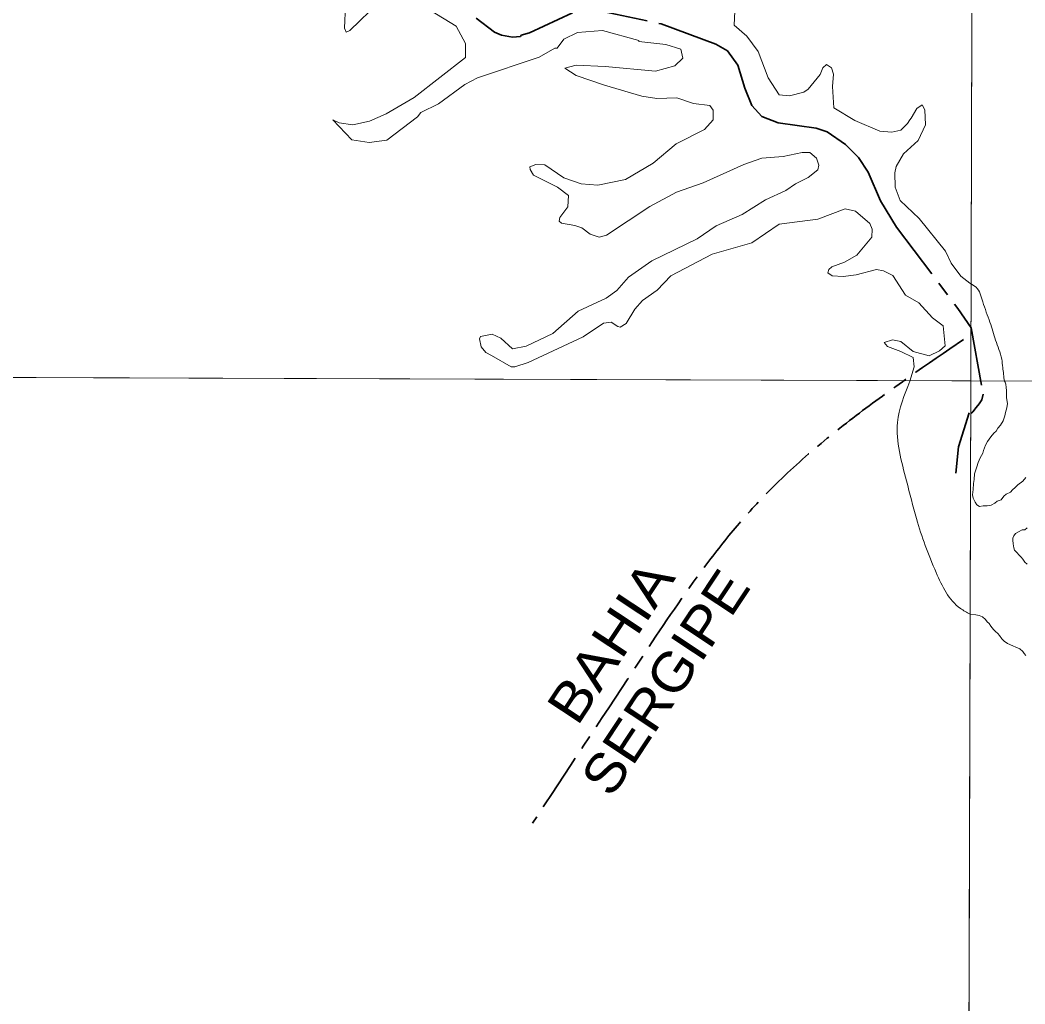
# Model space of a CAD drawing. Extents: x 553962 to 842807, y 8883888 to 9032388.
# Drawn here: x 583659 to 585726, y 8908688 to 8910712 of the extents above; entities that cross this region are included whole.
import ezdxf
from ezdxf.enums import TextEntityAlignment as Align

# ---------------------------------------------------------------- set-up
doc = ezdxf.new("R2010")
doc.units = 0
doc.header["$LTSCALE"] = 20
doc.linetypes.add('LONG_DASH_SHORT_DASH', pattern=[9.9, 6, -1.2, 1.5, -1.2])
doc.layers.add('6', color=7, linetype='Continuous', lineweight=13)

msp = doc.modelspace()

# ---------------------------------------------------------------- linework, layer by layer
at = {"layer": '6'}
msp.add_line((574653.9, 8910009.29), (626625.69, 8909822.11), dxfattribs=at)
for points in [[(585656.26, 8924738.82), (585614.83, 8909969.81), (585573.59, 8896026.67)], [(584328.75, 8910742.2), (584326.05, 8910695.42), (584329.47, 8910687.02), (584337.24, 8910690.76), (584398.25, 8910749.5)], [(584503.5, 8910731.62), (584555.75, 8910699.31), (584575.13, 8910664.28), (584575.02, 8910635.1)], [(585612.97, 8910170.9), (585594.11, 8910185.16), (585574.09, 8910212.04), (585562.34, 8910236.88), (585508.44, 8910303.84), (585469.46, 8910341.12), (585459.33, 8910368.41), (585458.58, 8910397.75), (585461.4, 8910410.82), (585476.19, 8910437.08), (585506.45, 8910464.72), (585521.45, 8910496.51), (585520.28, 8910527.37), (585514.35, 8910537.49), (585503.57, 8910530.23), (585491.92, 8910510.03), (585489.28, 8910507.15), (585484.33, 8910499.43), (585470.58, 8910485.7), (585452.07, 8910481.46), (585427.79, 8910483.5), (585376, 8910505.35), (585332.84, 8910531.94), (585330.25, 8910575.43), (585332.35, 8910601.01), (585328.23, 8910613.73), (585318.16, 8910620.76), (585310.2, 8910613.96), (585304.71, 8910600.14), (585280.34, 8910570.13), (585271.28, 8910563.7), (585242.03, 8910556.07), (585220.21, 8910558.26), (585197.63, 8910593.2), (585177.13, 8910647.82), (585153.96, 8910678.88), (585128, 8910701.85), (585128.95, 8910730.56)], [(584575.02, 8910635.1), (584469.84, 8910553.2), (584412.09, 8910519.15), (584378.09, 8910504.33), (584343.68, 8910496.84), (584315.57, 8910500.96), (584302.48, 8910506.73), (584341.71, 8910466.11), (584376.98, 8910460.03), (584413.37, 8910464.95), (584476.2, 8910513.28), (584483.17, 8910521.69), (584519.51, 8910539.61), (584574.11, 8910579.58), (584600.28, 8910593.54), (584727.06, 8910635.55), (584758.69, 8910654.18), (584764.08, 8910654.14), (584777.79, 8910672.81), (584805.81, 8910686.53), (584857.12, 8910690.46), (584931.57, 8910670.42), (584931.71, 8910668.32), (584987.38, 8910661.65), (585018.33, 8910652.23), (585022.51, 8910633.92), (585006.01, 8910617.94), (584965.81, 8910606.79), (584862.52, 8910616.69)], [(584862.52, 8910616.69), (584802.66, 8910619.36), (584779.5, 8910612.89), (584802.66, 8910598.34), (584860.95, 8910578.32), (584938.21, 8910555.28), (584968.78, 8910550.66), (585009.72, 8910551.97), (585044.2, 8910540.77), (585078.09, 8910536.29), (585084.57, 8910527.01), (585084.59, 8910506.68), (585066.64, 8910486.86), (585008.8, 8910457.75), (584961.03, 8910417.67), (584904.52, 8910384.19), (584847.68, 8910372.39), (584813.29, 8910375.47), (584777.62, 8910387.79), (584738.31, 8910414.55), (584719.64, 8910414.96), (584707.26, 8910410.11), (584708.33, 8910404.72), (584715.33, 8910392.87), (584764.79, 8910368.33), (584787.39, 8910351.36), (584785.88, 8910327.61), (584769.15, 8910305.77), (584767.63, 8910298.79), (584772.93, 8910294.41), (584799.96, 8910289.52), (584814.68, 8910285.05), (584831.64, 8910271.68), (584850.3, 8910265.57), (584865.49, 8910269.35), (584954.52, 8910328.54), (585009.6, 8910357.88), (585064.11, 8910377.56), (585147.91, 8910415.19), (585184.6, 8910428.28), (585228.51, 8910431.68), (585267.91, 8910439.73), (585283.87, 8910439.77), (585297.28, 8910428.06), (585301.75, 8910413.59), (585299.85, 8910403.97), (585279.93, 8910388.42), (585254.08, 8910375.57), (585234.39, 8910361.69), (585192.49, 8910342.55), (585144.05, 8910312.13), (585090.77, 8910288.98), (585052.06, 8910261.78), (584958.3, 8910216.92), (584910.47, 8910183.49), (584886.49, 8910155.56), (584864.3, 8910139.81), (584806.89, 8910113.37), (584754.65, 8910067.16), (584700.02, 8910041.57), (584672.19, 8910035.89), (584648.26, 8910057.92), (584630.36, 8910065.65), (584605.94, 8910060.97), (584603.9, 8910056.13)], [(584603.9, 8910056.13), (584607.2, 8910039.79), (584616.9, 8910028.47), (584628.53, 8910021.95), (584668.85, 8909998.86), (584676.74, 8909998.88), (584704.02, 8910007.58), (584817.19, 8910060.35), (584858.83, 8910088.51), (584875.08, 8910090.6), (584888.6, 8910081.71), (584893.45, 8910080.63), (584905.83, 8910087.97), (584923.73, 8910117.36), (584939.25, 8910135.54), (584969.7, 8910156.57), (584997.68, 8910186.26), (585082.52, 8910230.42), (585164.16, 8910253.97), (585220.57, 8910292.08), (585299.86, 8910302.46), (585355.9, 8910323.67), (585377.14, 8910318.93), (585407.14, 8910293.74), (585411.84, 8910281.76), (585411.33, 8910265.84), (585380.05, 8910228.29), (585354.76, 8910214.08), (585328.67, 8910204.35), (585322.97, 8910199.01), (585320.56, 8910192.25), (585329.24, 8910186.23), (585351.89, 8910184.51), (585378.77, 8910187.85), (585420.44, 8910199.13), (585435.03, 8910196.43)], [(585435.03, 8910196.43), (585454.14, 8910186.89), (585480.41, 8910146.25), (585507.61, 8910130.17), (585536, 8910099.43), (585557.68, 8910083.28), (585561.63, 8910042.24), (585550.13, 8910031.89), (585529.2, 8910021.46), (585495.77, 8910030.14), (585470.4, 8910050.78), (585453.42, 8910054.18), (585436.73, 8910048.71), (585443.64, 8910040.36), (585470.88, 8910030.24), (585495.82, 8910017.98), (585497.84, 8909999.02), (585489.29, 8909968.99)], [(585620.41, 8909758.53), (585621.71, 8909766.99), (585622.36, 8909778.71), (585626.92, 8909793.03), (585629.53, 8909802.15), (585634.09, 8909811.26), (585639.3, 8909821.03), (585640.6, 8909826.89), (585645.16, 8909837.31), (585649.07, 8909845.12), (585655.59, 8909854.88), (585662.1, 8909862.05), (585666.66, 8909866.6), (585669.92, 8909872.46), (585675.78, 8909878.97), (585681, 8909887.44), (585684.91, 8909897.85), (585686.21, 8909905.02), (585688.81, 8909914.13), (585690.12, 8909923.25), (585688.04, 8909935.05), (585688.08, 8909940.06), (585688.11, 8909944.06), (585688.15, 8909950.07), (585687.7, 8909956.08), (585686.75, 8909963.1), (585685.28, 8909967.11), (585683.67, 8909969.29)], [(585727.9, 8909770.9), (585721.39, 8909763.74), (585721.39, 8909763.74), (585711.62, 8909755.92), (585705.75, 8909750.71), (585705.75, 8909750.71), (585700.54, 8909745.51), (585696.63, 8909740.95), (585687.51, 8909737.04), (585682.3, 8909732.48), (585677.09, 8909725.32), (585668.62, 8909722.72), (585664.06, 8909718.16), (585656.89, 8909714.25), (585648.42, 8909712.95), (585640.32, 8909712.55), (585632.78, 8909711.65), (585632.78, 8909711.65), (585626.92, 8909714.91), (585623.66, 8909720.11), (585623.66, 8909720.11), (585619.75, 8909728.58), (585618.45, 8909735.09), (585619.75, 8909746.16), (585620.41, 8909758.53)], [(585730.3, 8909592.82), (585725.83, 8909596.86), (585721.87, 8909602.89), (585718.4, 8909606.92), (585714.93, 8909610.95), (585708.47, 8909617.5), (585704.5, 8909621.53), (585703.04, 8909626.55), (585701.6, 8909634.57), (585701.16, 8909642.08), (585701.19, 8909646.59), (585703.23, 8909651.08), (585706.76, 8909655.57), (585712.79, 8909659.03), (585720.33, 8909663.49), (585725.83, 8909663.45), (585730.36, 8909667.43)], [(585613.39, 8909490.12), (585625.07, 8909488.82), (585631.98, 8909487.29), (585638.88, 8909484.61), (585645.01, 8909479.24), (585648.08, 8909474.26), (585652.68, 8909470.43), (585655.75, 8909465.07), (585655.75, 8909465.07), (585661.5, 8909458.17), (585661.5, 8909458.17), (585665.71, 8909454.34), (585670.5, 8909450.27), (585673.97, 8909446.24), (585678.42, 8909439.2), (585683.39, 8909434.66), (585690.25, 8909429.44), (585690.25, 8909429.44), (585700.82, 8909424.53), (585707.3, 8909421.98), (585715.28, 8909418.43), (585721.74, 8909412.88), (585724.71, 8909408.85), (585728.18, 8909404.82)]]:
    msp.add_lwpolyline(points, dxfattribs=at)
for points in [[(585645.85, 8921027.32), (574684.91, 8921064.73), (574653.9, 8910009.29), (585614.83, 8909969.81)], [(596575.77, 8909932.4), (585614.83, 8909969.81), (585583.82, 8898914.37), (596544.75, 8898874.89)]]:
    msp.add_lwpolyline(points, close=True, dxfattribs=at)
at = {"layer": '6', "linetype": 'LONG_DASH_SHORT_DASH', "lineweight": 35}
for points in [[(584831.74, 8910735.03), (584977.83, 8910704.34), (585090.24, 8910662.83), (585114.41, 8910648.58), (585135.65, 8910619.11), (585149.89, 8910572.09), (585164.58, 8910536.64), (585184.89, 8910513.71), (585218.41, 8910500.66), (585296.9, 8910489.89), (585319.39, 8910482.11), (585356.61, 8910456.13), (585383.37, 8910429.36), (585403.7, 8910399.53), (585428.8, 8910340.25), (585462.1, 8910286.21), (585588.31, 8910118.5), (585615.12, 8910078.72)], [(584597.3, 8910716.04), (584634.97, 8910687.05), (584649.24, 8910681), (584671.72, 8910677.11), (584688.53, 8910678.4), (584689.93, 8910681.43), (584707.22, 8910685.78), (584795.37, 8910727.25)], [(585615.12, 8910078.72), (585640.31, 8909942.82), (585637.22, 8909930.81), (585631.66, 8909922.33), (585625.6, 8909914.85), (585619.04, 8909906.37), (585614.61, 8909902.82)], [(585583.67, 8909780.13), (585589.52, 8909834.37), (585611.07, 8909903.91)]]:
    msp.add_lwpolyline(points, dxfattribs=at)
at = {"layer": '6'}
for points in [[(585683.67, 8909969.29), (585680.45, 8909997.42), (585678.16, 8910014.63), (585665.54, 8910053.64), (585654.06, 8910090.36), (585639.15, 8910132.81), (585625.38, 8910162.65), (585612.97, 8910170.9)], [(585489.29, 8909968.99), (585463.88, 8909884.32), (585482.37, 8909764.16), (585502.7, 8909686.51), (585543.37, 8909575.59), (585593.29, 8909501.65), (585613.39, 8909490.12)]]:
    msp.add_spline(points, degree=3, dxfattribs=at)
at = {"layer": '6', "linetype": 'LONG_DASH_SHORT_DASH', "lineweight": 35}
msp.add_spline([(585599.5, 8910054.8), (585178.75, 8909721.74), (584922.23, 8909376.82), (584712.92, 8909059.85)], degree=3, dxfattribs=at)

# ---------------------------------------------------------------- texts
at = {"layer": '6'}
for s, width, p in [('BAHIA', 1.15, (584907.18, 8909411.3)), ('SERGIPE', 1.1, (585019.57, 8909327.44))]:
    msp.add_text(s, height=80, rotation=56.48, dxfattribs=dict(at, width=width)).set_placement(p, align=Align.CENTER)

doc.saveas('drawing.dxf')
